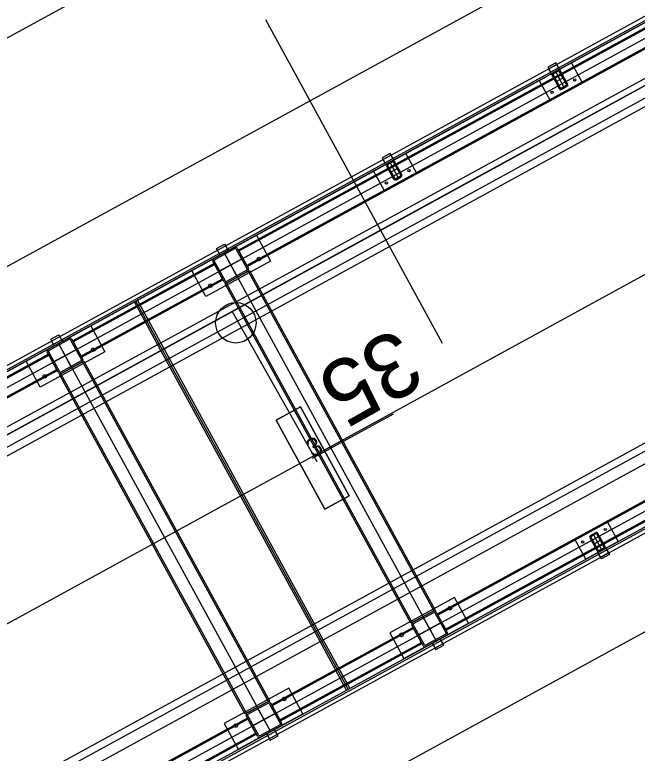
# Model space of a CAD drawing. Extents: x -783978 to -783565, y -1064821 to -1064596.
# Drawn here: x -783753.539 to -783750.16, y -1064676.556 to -1064672.55 of the extents above; entities that cross this region are included whole.
import ezdxf

# ---------------------------------------------------------------- set-up
doc = ezdxf.new("R2010")
doc.units = 0
for name, color, linetype in [('Default', 7, 'Continuous'), ('SO 01_11_01', 7, 'Continuous'), ('SO 01_20_01', 7, 'Continuous'), ('SO 01_50_01', 7, 'Continuous'), ('SO 01_74_01', 7, 'Continuous'), ('SO 01_86_04', 7, 'Continuous')]:
    doc.layers.add(name, color=color, linetype=linetype)

# ---------------------------------------------------------------- blocks, each defined once
blk = doc.blocks.new('POINT_DISPLAY')
at = {"layer": 'Default'}
blk.add_line((0, 0), (0, 0), dxfattribs=at)

msp = doc.modelspace()

# ---------------------------------------------------------------- linework, layer by layer
at = {"layer": 'SO 01_11_01'}
msp.add_line((-783772.8819, -1064683.2217), (-783730.898, -1064660.279), dxfattribs=at)
at = {"layer": 'SO 01_20_01'}
for p, q in [((-783735.0054, -1064663.7532), (-783787.4671, -1064692.4555)), ((-783735.2041, -1064664.4318), (-783786.7885, -1064692.6541)), ((-783786.6445, -1064692.9173), (-783735.3233, -1064664.839)), ((-783738.0171, -1064666.3812), (-783786.4402, -1064692.874)), ((-783786.421, -1064692.9091), (-783737.9979, -1064666.4163)), ((-783737.8741, -1064667.2605), (-783785.3352, -1064693.2269)), ((-783785.6531, -1064694.3127), (-783737.23, -1064667.82)), ((-783737.0912, -1064667.858), (-783785.7805, -1064694.4964)), ((-783737.2108, -1064667.855), (-783785.6339, -1064694.3478)), ((-783785.6366, -1064694.7596), (-783736.9472, -1064668.1212)), ((-783746.2961, -1064673.8055), (-783785.8354, -1064695.4379)), ((-783752.7462, -1064674.3713), (-783752.8902, -1064674.1081)), ((-783751.7295, -1064676.2087), (-783752.8814, -1064674.1033)), ((-783752.7287, -1064674.3617), (-783752.8727, -1064674.0985)), ((-783751.8647, -1064675.9408), (-783752.7287, -1064674.3617)), ((-783751.8823, -1064675.9504), (-783752.7462, -1064674.3713)), ((-783751.7383, -1064676.2135), (-783751.8823, -1064675.9504)), ((-783751.7207, -1064676.2039), (-783751.8647, -1064675.9408))]:
    msp.add_line(p, q, dxfattribs=at)
at = {"layer": 'SO 01_50_01'}
for p, q in [((-783786.7885, -1064692.6541), (-783725.4827, -1064659.1131)), ((-783751.6971, -1064673.4553), (-783747.3107, -1064671.0555)), ((-783751.6971, -1064673.4554), (-783747.3106, -1064671.0555)), ((-783751.6971, -1064673.4554), (-783747.3106, -1064671.0555)), ((-783751.2171, -1064674.3326), (-783752.1771, -1064672.578)), ((-783756.0835, -1064675.8552), (-783751.6971, -1064673.4553)), ((-783756.0835, -1064675.8552), (-783751.6971, -1064673.4554)), ((-783756.0835, -1064675.8552), (-783751.6971, -1064673.4554))]:
    msp.add_line(p, q, dxfattribs=at)
at = {"layer": 'SO 01_74_01'}
for p, q in [((-783735.2185, -1064664.4055), (-783786.6099, -1064692.5222)), ((-783786.6003, -1064692.5398), (-783735.2089, -1064664.423)), ((-783749.7594, -1064672.4237), (-783752.3255, -1064673.8276)), ((-783749.7564, -1064672.4292), (-783752.3224, -1064673.8331)), ((-783752.2805, -1064673.9098), (-783749.7144, -1064672.5059)), ((-783752.2775, -1064673.9153), (-783749.7114, -1064672.5114)), ((-783750.6021, -1064672.8106), (-783750.646, -1064672.8346)), ((-783750.646, -1064672.8346), (-783750.6268, -1064672.8697)), ((-783750.5973, -1064672.8194), (-783750.6412, -1064672.8434)), ((-783750.6412, -1064672.8434), (-783750.6316, -1064672.8609)), ((-783750.6316, -1064672.8609), (-783750.5877, -1064672.8369)), ((-783750.5829, -1064672.8457), (-783750.6021, -1064672.8106)), ((-783750.5877, -1064672.8369), (-783750.5973, -1064672.8194)), ((-783750.6268, -1064672.8697), (-783750.5829, -1064672.8457)), ((-783785.4388, -1064694.6628), (-783745.8293, -1064672.9921)), ((-783745.8197, -1064673.0096), (-783785.4292, -1064694.6803)), ((-783751.5013, -1064673.3026), (-783751.5452, -1064673.3266)), ((-783751.4965, -1064673.3114), (-783751.5404, -1064673.3354)), ((-783751.4821, -1064673.3377), (-783751.5013, -1064673.3026)), ((-783751.4869, -1064673.3289), (-783751.4965, -1064673.3114)), ((-783751.5452, -1064673.3266), (-783751.526, -1064673.3617)), ((-783751.5404, -1064673.3354), (-783751.5308, -1064673.3529)), ((-783751.5308, -1064673.3529), (-783751.4869, -1064673.3289)), ((-783751.526, -1064673.3617), (-783751.4821, -1064673.3377)), ((-783752.4444, -1064673.8186), (-783752.4005, -1064673.7946)), ((-783752.4005, -1064673.7946), (-783752.3813, -1064673.8296)), ((-783752.4252, -1064673.8536), (-783752.4444, -1064673.8186)), ((-783752.3813, -1064673.8296), (-783752.4252, -1064673.8536)), ((-783752.3255, -1064673.8276), (-783752.2775, -1064673.9153)), ((-783752.3224, -1064673.8331), (-783752.2805, -1064673.9098)), ((-783752.4571, -1064673.8996), (-783753.2247, -1064674.3196)), ((-783752.454, -1064673.9051), (-783753.2217, -1064674.3251)), ((-783752.4091, -1064673.9873), (-783752.4571, -1064673.8996)), ((-783752.4121, -1064673.9818), (-783752.454, -1064673.9051)), ((-783752.3971, -1064674.0092), (-783752.2655, -1064673.9372)), ((-783752.39, -1064674.0054), (-783752.2725, -1064673.9411)), ((-783752.2725, -1064673.9411), (-783751.2645, -1064675.7834)), ((-783752.2655, -1064673.9372), (-783751.2575, -1064675.7795)), ((-783753.1798, -1064674.4018), (-783752.4121, -1064673.9818)), ((-783753.1767, -1064674.4073), (-783752.4091, -1064673.9873)), ((-783751.3821, -1064675.8477), (-783752.39, -1064674.0054)), ((-783751.3891, -1064675.8515), (-783752.3971, -1064674.0092)), ((-783753.3437, -1064674.3106), (-783753.2998, -1064674.2866)), ((-783753.2998, -1064674.2866), (-783753.2806, -1064674.3217)), ((-783753.3245, -1064674.3457), (-783753.3437, -1064674.3106)), ((-783753.2806, -1064674.3217), (-783753.3245, -1064674.3457)), ((-783753.2247, -1064674.3196), (-783753.1767, -1064674.4073)), ((-783753.2217, -1064674.3251), (-783753.1798, -1064674.4018)), ((-783753.3563, -1064674.3916), (-783755.9224, -1064675.7955)), ((-783753.3533, -1064674.3971), (-783755.9194, -1064675.801)), ((-783753.3083, -1064674.4793), (-783753.3563, -1064674.3916)), ((-783753.3114, -1064674.4738), (-783753.3533, -1064674.3971)), ((-783748.6795, -1064674.3976), (-783751.2455, -1064675.8015)), ((-783748.6764, -1064674.4031), (-783751.2425, -1064675.807)), ((-783753.2963, -1064674.5012), (-783753.1647, -1064674.4292)), ((-783753.2893, -1064674.4974), (-783753.1718, -1064674.4331)), ((-783753.1718, -1064674.4331), (-783752.1638, -1064676.2754)), ((-783753.1647, -1064674.4292), (-783752.1568, -1064676.2715)), ((-783755.8774, -1064675.8777), (-783753.3114, -1064674.4738)), ((-783755.8744, -1064675.8832), (-783753.3083, -1064674.4793)), ((-783751.2006, -1064675.8837), (-783748.6345, -1064674.4798)), ((-783751.1975, -1064675.8892), (-783748.6315, -1064674.4853)), ((-783752.2884, -1064676.3435), (-783753.2963, -1064674.5012)), ((-783752.2814, -1064676.3397), (-783753.2893, -1064674.4974)), ((-783750.374, -1064675.4672), (-783750.3302, -1064675.4432)), ((-783750.3302, -1064675.4432), (-783750.311, -1064675.4783)), ((-783750.3548, -1064675.5023), (-783750.374, -1064675.4672)), ((-783750.3692, -1064675.4759), (-783750.3254, -1064675.4519)), ((-783750.3596, -1064675.4935), (-783750.3692, -1064675.4759)), ((-783750.3158, -1064675.4695), (-783750.3596, -1064675.4935)), ((-783750.311, -1064675.4783), (-783750.3548, -1064675.5023)), ((-783750.3254, -1064675.4519), (-783750.3158, -1064675.4695)), ((-783751.2575, -1064675.7795), (-783751.3891, -1064675.8515)), ((-783751.2645, -1064675.7834), (-783751.3821, -1064675.8477)), ((-783751.2455, -1064675.8015), (-783751.1975, -1064675.8892)), ((-783751.2425, -1064675.807), (-783751.2006, -1064675.8837)), ((-783751.3771, -1064675.8735), (-783752.1448, -1064676.2935)), ((-783751.3741, -1064675.879), (-783752.1418, -1064676.299)), ((-783751.3291, -1064675.9612), (-783751.3771, -1064675.8735)), ((-783751.3321, -1064675.9557), (-783751.3741, -1064675.879)), ((-783752.0998, -1064676.3757), (-783751.3321, -1064675.9557)), ((-783752.0968, -1064676.3812), (-783751.3291, -1064675.9612)), ((-783751.2294, -1064675.9351), (-783751.2733, -1064675.9591)), ((-783751.2733, -1064675.9591), (-783751.2541, -1064675.9942)), ((-783751.2541, -1064675.9942), (-783751.2102, -1064675.9702)), ((-783751.2102, -1064675.9702), (-783751.2294, -1064675.9351)), ((-783752.1568, -1064676.2715), (-783752.2884, -1064676.3435)), ((-783752.1638, -1064676.2754), (-783752.2814, -1064676.3397)), ((-783752.1448, -1064676.2935), (-783752.0968, -1064676.3812)), ((-783752.1418, -1064676.299), (-783752.0998, -1064676.3757)), ((-783752.2764, -1064676.3655), (-783754.8425, -1064677.7694)), ((-783752.2734, -1064676.371), (-783754.8394, -1064677.7749)), ((-783752.2284, -1064676.4532), (-783752.2764, -1064676.3655)), ((-783752.2314, -1064676.4477), (-783752.2734, -1064676.371)), ((-783754.7975, -1064677.8516), (-783752.2314, -1064676.4477)), ((-783752.1287, -1064676.4271), (-783752.1725, -1064676.4511)), ((-783752.1725, -1064676.4511), (-783752.1533, -1064676.4862)), ((-783752.1095, -1064676.4622), (-783752.1287, -1064676.4271)), ((-783754.7945, -1064677.8571), (-783752.2284, -1064676.4532)), ((-783752.1533, -1064676.4862), (-783752.1095, -1064676.4622))]:
    msp.add_line(p, q, dxfattribs=at)
for points in [[(-783735.1681, -1064664.4976), (-783787.4762, -1064693.1159)], [(-783734.0882, -1064666.4715), (-783786.3963, -1064695.0898)], [(-783750.6222, -1064672.878), (-783750.5833, -1064672.9491)], [(-783750.5912, -1064672.8502), (-783750.6185, -1064672.8652)], [(-783750.6167, -1064672.875), (-783750.5778, -1064672.9461)], [(-783750.5882, -1064672.8558), (-783750.6154, -1064672.8707)], [(-783750.6048, -1064672.8577), (-783750.5568, -1064672.9454)], [(-783750.545, -1064672.9282), (-783750.5839, -1064672.857)], [(-783750.5394, -1064672.9251), (-783750.5784, -1064672.854)], [(-783750.5589, -1064672.8896), (-783750.6028, -1064672.9136)], [(-783750.5735, -1064672.9474), (-783750.5462, -1064672.9324)], [(-783750.5705, -1064672.9529), (-783750.5432, -1064672.938)], [(-783751.4904, -1064673.3422), (-783751.5177, -1064673.3571)], [(-783751.4874, -1064673.3477), (-783751.5147, -1064673.3627)], [(-783751.504, -1064673.3497), (-783751.456, -1064673.4374)], [(-783751.4442, -1064673.4201), (-783751.4831, -1064673.349)], [(-783751.4386, -1064673.4171), (-783751.4776, -1064673.346)], [(-783751.5214, -1064673.37), (-783751.4825, -1064673.4411)], [(-783751.5159, -1064673.3669), (-783751.477, -1064673.4381)], [(-783751.4581, -1064673.3815), (-783751.502, -1064673.4055)], [(-783751.4727, -1064673.4393), (-783751.4454, -1064673.4244)], [(-783751.4697, -1064673.4449), (-783751.4424, -1064673.4299)], [(-783752.4585, -1064673.8719), (-783752.348, -1064673.8114)], [(-783752.4547, -1064673.8789), (-783752.3441, -1064673.8184)], [(-783752.4033, -1064673.8416), (-783751.2513, -1064675.9471)], [(-783752.4033, -1064673.8416), (-783752.3313, -1064673.9732)], [(-783752.3387, -1064673.82), (-783752.2782, -1064673.9306)], [(-783752.3317, -1064673.8162), (-783752.2712, -1064673.9267)], [(-783752.3958, -1064673.9949), (-783752.4563, -1064673.8843)], [(-783752.3015, -1064673.8714), (-783752.4331, -1064673.9434)], [(-783752.4028, -1064673.9987), (-783752.4633, -1064673.8882)], [(-783752.2798, -1064673.936), (-783752.3904, -1064673.9965)], [(-783752.276, -1064673.943), (-783752.3865, -1064674.0035)], [(-783753.3578, -1064674.3639), (-783753.2473, -1064674.3034)], [(-783753.354, -1064674.3709), (-783753.2434, -1064674.3104)], [(-783753.238, -1064674.312), (-783753.1775, -1064674.4226)], [(-783753.231, -1064674.3082), (-783753.1705, -1064674.4187)], [(-783753.2007, -1064674.3635), (-783753.3323, -1064674.4354)], [(-783753.3025, -1064674.3337), (-783752.1506, -1064676.4391)], [(-783753.3025, -1064674.3337), (-783753.2305, -1064674.4652)], [(-783753.3021, -1064674.4907), (-783753.3626, -1064674.3802)], [(-783753.2951, -1064674.4869), (-783753.3556, -1064674.3763)], [(-783753.1791, -1064674.428), (-783753.2897, -1064674.4885)], [(-783753.1753, -1064674.435), (-783753.2858, -1064674.4955)], [(-783750.3865, -1064675.36), (-783750.4138, -1064675.3749)], [(-783750.3834, -1064675.3655), (-783750.4107, -1064675.3804)], [(-783750.4001, -1064675.3674), (-783750.3521, -1064675.4552)], [(-783750.3402, -1064675.4379), (-783750.3792, -1064675.3667)], [(-783750.3347, -1064675.4349), (-783750.3736, -1064675.3637)], [(-783750.4175, -1064675.3877), (-783750.3786, -1064675.4589)], [(-783750.412, -1064675.3847), (-783750.3731, -1064675.4558)], [(-783750.3542, -1064675.3993), (-783750.398, -1064675.4233)], [(-783750.3688, -1064675.4571), (-783750.3415, -1064675.4422)], [(-783750.3658, -1064675.4626), (-783750.3385, -1064675.4477)], [(-783751.3786, -1064675.8458), (-783751.2681, -1064675.7853)], [(-783751.3748, -1064675.8528), (-783751.2642, -1064675.7923)], [(-783751.2588, -1064675.7939), (-783751.1983, -1064675.9044)], [(-783751.2518, -1064675.7901), (-783751.1913, -1064675.9006)], [(-783751.2215, -1064675.8453), (-783751.3531, -1064675.9173)], [(-783751.3233, -1064675.8155), (-783751.2513, -1064675.9471)], [(-783751.3229, -1064675.9726), (-783751.3834, -1064675.8621)], [(-783751.3159, -1064675.9688), (-783751.3763, -1064675.8582)], [(-783751.1999, -1064675.9099), (-783751.3104, -1064675.9704)], [(-783751.1961, -1064675.9169), (-783751.3066, -1064675.9774)], [(-783752.2779, -1064676.3378), (-783752.1673, -1064676.2773)], [(-783752.274, -1064676.3448), (-783752.1635, -1064676.2843)], [(-783752.1581, -1064676.2859), (-783752.0976, -1064676.3965)], [(-783752.151, -1064676.2821), (-783752.0906, -1064676.3926)], [(-783752.2226, -1064676.3075), (-783752.1506, -1064676.4391)], [(-783752.2222, -1064676.4646), (-783752.2826, -1064676.3541)], [(-783752.2151, -1064676.4608), (-783752.2756, -1064676.3502)], [(-783752.1208, -1064676.3373), (-783752.2524, -1064676.4093)], [(-783752.0992, -1064676.4019), (-783752.2097, -1064676.4624)], [(-783752.0953, -1064676.4089), (-783752.2059, -1064676.4694)]]:
    msp.add_lwpolyline(points, dxfattribs=at)
for points in [[(-783750.5171, -1064672.8097), (-783750.6926, -1064672.9057), (-783750.635, -1064673.011), (-783750.4595, -1064672.915)], [(-783750.5829, -1064672.8457), (-783750.6268, -1064672.8697), (-783750.5788, -1064672.9574), (-783750.5349, -1064672.9334)], [(-783751.4163, -1064673.3017), (-783751.5918, -1064673.3977), (-783751.5342, -1064673.5029), (-783751.3587, -1064673.407)], [(-783752.151, -1064673.886), (-783752.5019, -1064674.078), (-783752.5787, -1064673.9376), (-783752.2278, -1064673.7457)], [(-783753.0503, -1064674.378), (-783753.4012, -1064674.57), (-783753.478, -1064674.4296), (-783753.1271, -1064674.2377)], [(-783750.2644, -1064675.4072), (-783750.4398, -1064675.5032), (-783750.4974, -1064675.3979), (-783750.322, -1064675.3019)], [(-783751.1527, -1064675.7108), (-783751.5036, -1064675.9028), (-783751.4268, -1064676.0431), (-783751.0759, -1064675.8511)], [(-783752.0519, -1064676.2028), (-783752.4029, -1064676.3948), (-783752.3261, -1064676.5351), (-783751.9752, -1064676.3431)]]:
    msp.add_lwpolyline(points, close=True, dxfattribs=at)
for centre, radius in [((-783750.5002, -1064672.9031), 0.006), ((-783750.623, -1064672.9703), 0.006), ((-783751.3994, -1064673.395), 0.006), ((-783751.5223, -1064673.4622), 0.006), ((-783752.2141, -1064673.8749), 0.01), ((-783752.4773, -1064674.0189), 0.01), ((-783753.1133, -1064674.3669), 0.01), ((-783753.3765, -1064674.5109), 0.01), ((-783750.3339, -1064675.3426), 0.006), ((-783750.4567, -1064675.4098), 0.006), ((-783751.1773, -1064675.7699), 0.01), ((-783751.4405, -1064675.9139), 0.01), ((-783752.0766, -1064676.2619), 0.01), ((-783752.3398, -1064676.4059), 0.01)]:
    msp.add_circle(centre, radius, dxfattribs=at)
for centre, radius, start, end in [((-783750.6139, -1064672.8735), 0.00945, 118.6835, 208.6835), ((-783750.6139, -1064672.8735), 0.00315, 118.6835, 208.6835), ((-783750.5866, -1064672.8585), 0.00945, 28.6835, 118.6835), ((-783750.5866, -1064672.8585), 0.00315, 28.6835, 118.6835), ((-783750.5477, -1064672.9297), 0.00945, 298.6835, 28.6835), ((-783750.575, -1064672.9446), 0.00945, 208.6835, 298.6835), ((-783750.575, -1064672.9446), 0.00315, 208.6835, 298.6835), ((-783750.5477, -1064672.9297), 0.00315, 298.6835, 28.6835), ((-783751.5131, -1064673.3654), 0.00945, 118.6835, 208.6835), ((-783751.5131, -1064673.3654), 0.00315, 118.6835, 208.6835), ((-783751.4859, -1064673.3505), 0.00945, 28.6835, 118.6835), ((-783751.4859, -1064673.3505), 0.00315, 28.6835, 118.6835), ((-783751.4742, -1064673.4366), 0.00945, 208.6835, 298.6835), ((-783751.4742, -1064673.4366), 0.00315, 208.6835, 298.6835), ((-783751.4469, -1064673.4217), 0.00315, 298.6835, 28.6835), ((-783751.4469, -1064673.4217), 0.00945, 298.6835, 28.6835), ((-783752.3422, -1064673.8219), 0.012, 28.6835, 118.6835), ((-783752.3422, -1064673.8219), 0.004, 28.6835, 118.6835), ((-783752.4528, -1064673.8824), 0.012, 118.6835, 208.6835), ((-783752.4528, -1064673.8824), 0.004, 118.6835, 208.6835), ((-783752.2818, -1064673.9325), 0.012, 298.6835, 28.6835), ((-783752.2818, -1064673.9325), 0.004, 298.6835, 28.6835), ((-783752.3923, -1064673.993), 0.012, 208.6835, 298.6835), ((-783752.3923, -1064673.993), 0.004, 208.6835, 298.6835), ((-783753.2415, -1064674.3139), 0.012, 28.6835, 118.6835), ((-783753.2415, -1064674.3139), 0.004, 28.6835, 118.6835), ((-783753.352, -1064674.3744), 0.012, 118.6835, 208.6835), ((-783753.352, -1064674.3744), 0.004, 118.6835, 208.6835), ((-783753.181, -1064674.4245), 0.004, 298.6835, 28.6835), ((-783753.181, -1064674.4245), 0.012, 298.6835, 28.6835), ((-783753.2916, -1064674.485), 0.004, 208.6835, 298.6835), ((-783753.2916, -1064674.485), 0.012, 208.6835, 298.6835), ((-783750.3819, -1064675.3683), 0.00945, 28.6835, 118.6835), ((-783750.3819, -1064675.3683), 0.00315, 28.6835, 118.6835), ((-783750.4092, -1064675.3832), 0.00945, 118.6835, 208.6835), ((-783750.4092, -1064675.3832), 0.00315, 118.6835, 208.6835), ((-783750.343, -1064675.4394), 0.00315, 298.6835, 28.6835), ((-783750.343, -1064675.4394), 0.00945, 298.6835, 28.6835), ((-783750.3703, -1064675.4543), 0.00945, 208.6835, 298.6835), ((-783750.3703, -1064675.4543), 0.00315, 208.6835, 298.6835), ((-783751.2623, -1064675.7958), 0.012, 28.6835, 118.6835), ((-783751.2623, -1064675.7958), 0.004, 28.6835, 118.6835), ((-783751.3728, -1064675.8563), 0.012, 118.6835, 208.6835), ((-783751.3728, -1064675.8563), 0.004, 118.6835, 208.6835), ((-783751.2018, -1064675.9064), 0.004, 298.6835, 28.6835), ((-783751.2018, -1064675.9064), 0.012, 298.6835, 28.6835), ((-783751.3124, -1064675.9668), 0.004, 208.6835, 298.6835), ((-783751.3124, -1064675.9668), 0.012, 208.6835, 298.6835), ((-783752.1616, -1064676.2878), 0.012, 28.6835, 118.6835), ((-783752.1616, -1064676.2878), 0.004, 28.6835, 118.6835), ((-783752.2721, -1064676.3483), 0.012, 118.6835, 208.6835), ((-783752.2721, -1064676.3483), 0.004, 118.6835, 208.6835), ((-783752.1011, -1064676.3984), 0.004, 298.6835, 28.6835), ((-783752.1011, -1064676.3984), 0.012, 298.6835, 28.6835), ((-783752.2116, -1064676.4588), 0.012, 208.6835, 298.6835), ((-783752.2116, -1064676.4588), 0.004, 208.6835, 298.6835)]:
    msp.add_arc(centre, radius, start, end, dxfattribs=at)
at = {"layer": 'SO 01_86_04'}
for p, q in [((-783752.3591, -1064674.1595), (-783751.8989, -1064674.9741)), ((-783751.9885, -1064674.6778), (-783752.1201, -1064674.7498)), ((-783751.9885, -1064674.6778), (-783752.1201, -1064674.7498)), ((-783752.1201, -1064674.7498), (-783751.9885, -1064674.6778)), ((-783752.1201, -1064674.7498), (-783751.9885, -1064674.6778)), ((-783751.7245, -1064675.1603), (-783751.9885, -1064674.6778)), ((-783751.7245, -1064675.1603), (-783751.9885, -1064674.6778)), ((-783751.9885, -1064674.6778), (-783751.7245, -1064675.1603)), ((-783751.9885, -1064674.6778), (-783751.7245, -1064675.1603)), ((-783751.9223, -1064674.955), (-783751.4837, -1064674.715)), ((-783752.1201, -1064674.7498), (-783751.8561, -1064675.2323)), ((-783752.1201, -1064674.7498), (-783751.8561, -1064675.2323)), ((-783751.8561, -1064675.2323), (-783752.1201, -1064674.7498)), ((-783751.8561, -1064675.2323), (-783752.1201, -1064674.7498)), ((-783751.8561, -1064675.2323), (-783751.7245, -1064675.1603)), ((-783751.8561, -1064675.2323), (-783751.7245, -1064675.1603)), ((-783751.7245, -1064675.1603), (-783751.8561, -1064675.2323)), ((-783751.7245, -1064675.1603), (-783751.8561, -1064675.2323))]:
    msp.add_line(p, q, dxfattribs=at)
for points in [[(-783738.3222, -1064666.4797), (-783740.5325, -1064667.689), (-783743.1715, -1064669.1328), (-783745.7538, -1064670.5456), (-783748.4385, -1064672.0145), (-783751.0413, -1064673.4385), (-783753.6847, -1064674.8847), (-783756.3281, -1064676.3309), (-783758.9715, -1064677.7772), (-783761.6149, -1064679.2234), (-783764.2583, -1064680.6696), (-783766.9018, -1064682.1159), (-783769.4633, -1064683.5173), (-783772.109, -1064684.9648), (-783774.7882, -1064686.4306), (-783778.1382, -1064688.2722), (-783783.8139, -1064691.3971), (-783785.747, -1064692.4898)], [(-783747.063, -1064670.9765), (-783746.9575, -1064671.1681), (-783786.6893, -1064692.8619), (-783786.185, -1064693.7636)]]:
    msp.add_lwpolyline(points, dxfattribs=at)
msp.add_circle((-783752.3392, -1064674.221), 0.1097, dxfattribs=at)

# ---------------------------------------------------------------- block references
at = {"layer": 'SO 01_86_04', "xscale": 0.010000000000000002, "yscale": 0.009999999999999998, "rotation": 28.683491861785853}
for p in [(-783751.9885, -1064674.6778), (-783751.9885, -1064674.6778), (-783752.1201, -1064674.7498), (-783752.1201, -1064674.7498), (-783751.7245, -1064675.1603), (-783751.7245, -1064675.1603), (-783751.8561, -1064675.2323), (-783751.8561, -1064675.2323)]:
    msp.add_blockref('POINT_DISPLAY', p, dxfattribs=at)

# ---------------------------------------------------------------- texts
at = {"layer": 'SO 01_86_04'}
for s, height, rotation, p in [('35', 0.351, 209.46, (-783751.4654, -1064674.2401)), ('3', 0.1, 28.6835, (-783751.9223, -1064674.955))]:
    msp.add_text(s, height=height, rotation=rotation, dxfattribs=at).set_placement(p)

doc.saveas('drawing.dxf')
